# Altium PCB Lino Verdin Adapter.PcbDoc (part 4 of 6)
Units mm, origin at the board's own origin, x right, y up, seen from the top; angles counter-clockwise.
Board outline 69.6 x 35 mm, 8 copper layers (Top Layer, Mid 1, GND 1, Mid 2, Mid 3, GND 2, Mid 4, Bottom Layer), stack 1.198 mm thick; 208 components, 258 nets, 1063 pads, 1090 vias.
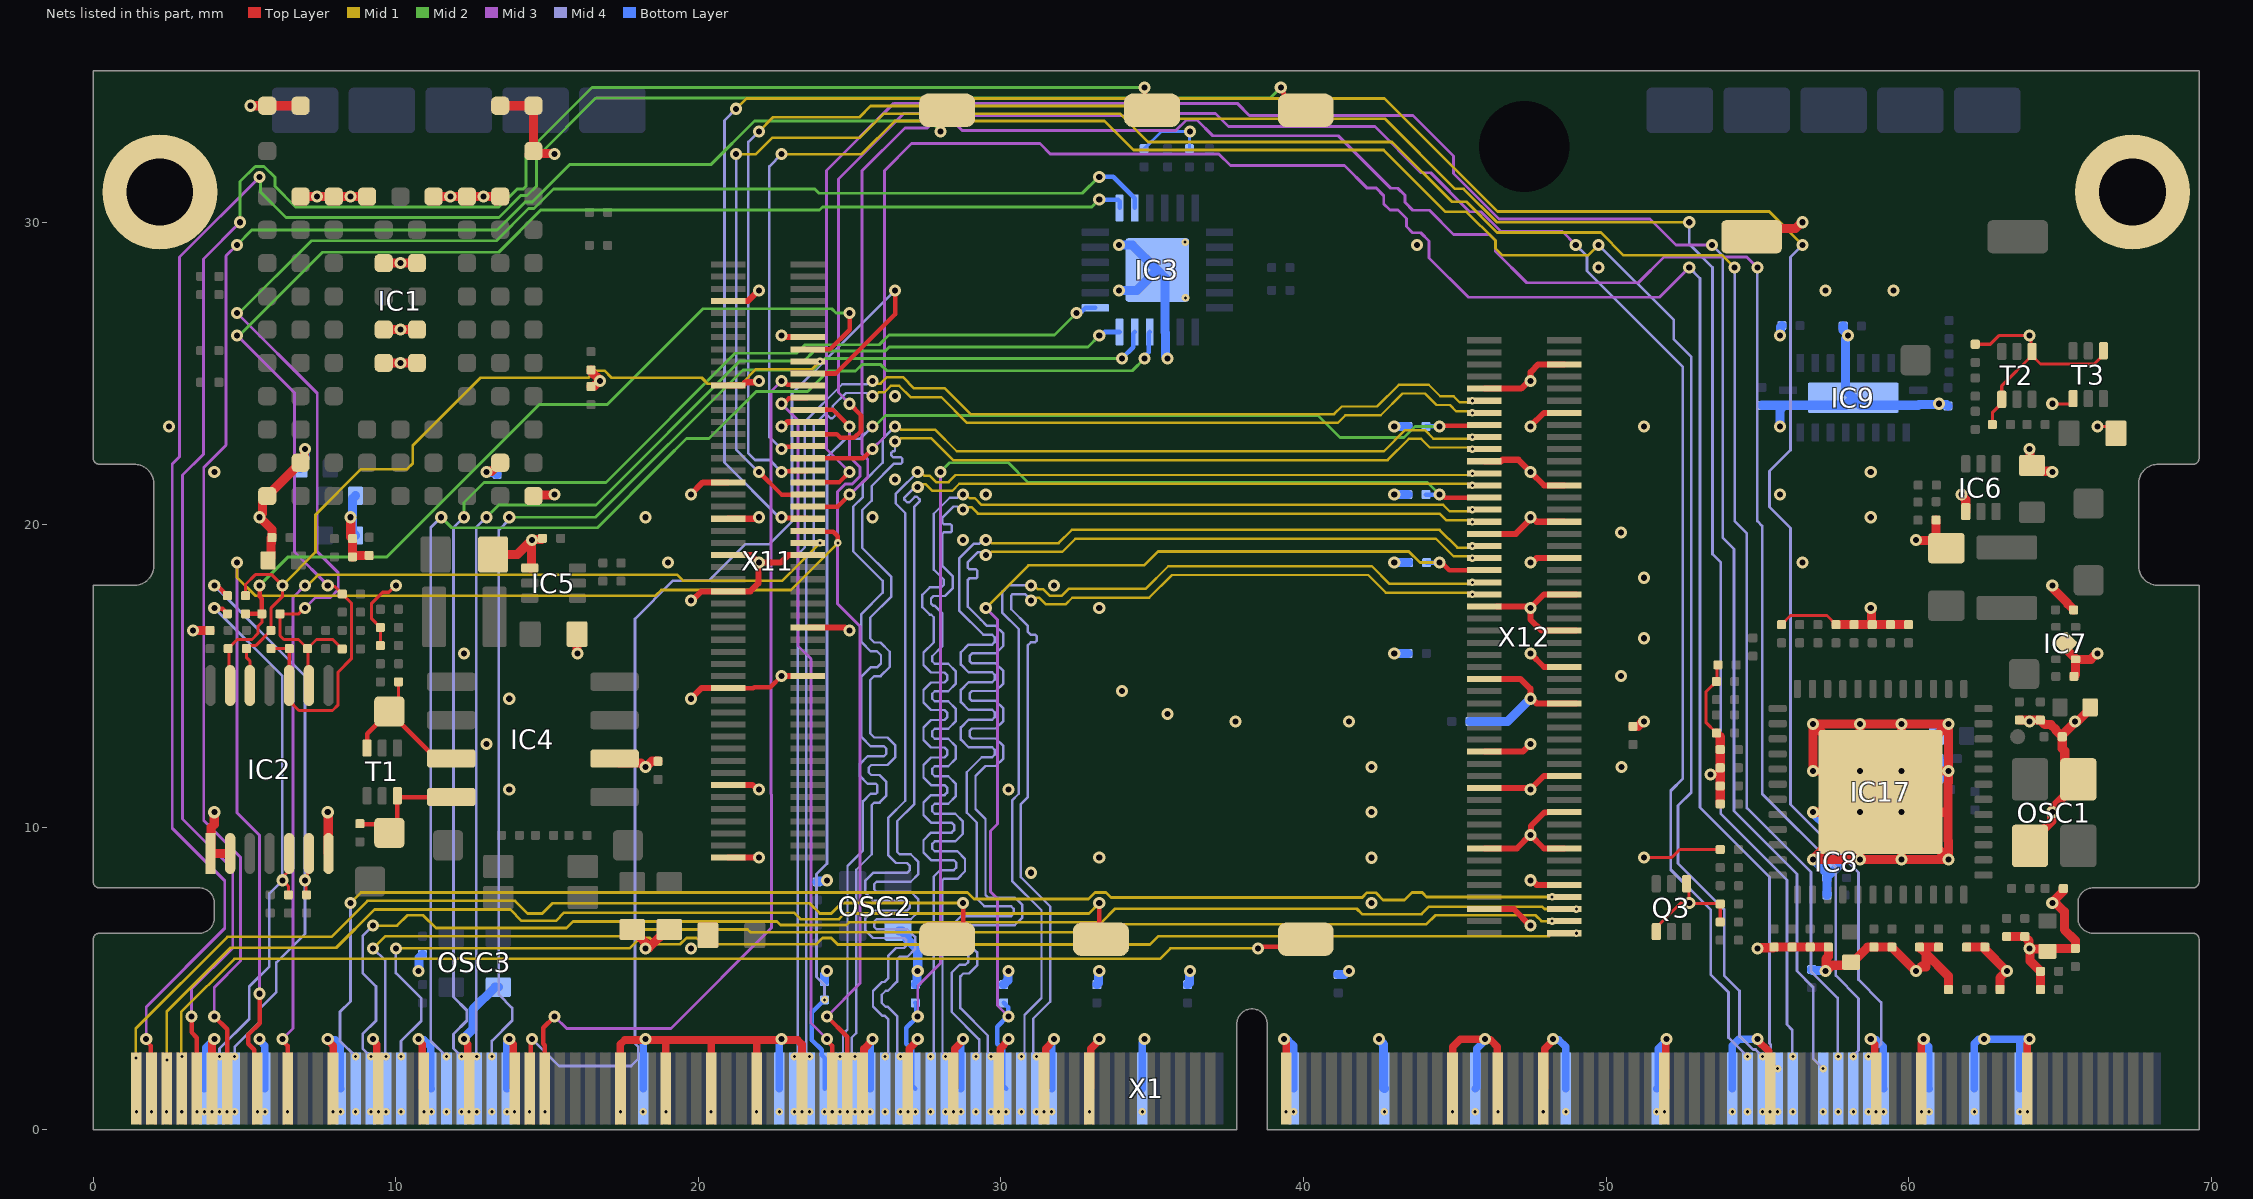
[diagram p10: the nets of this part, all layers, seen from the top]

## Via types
v1: diameter 0.4, hole 0.2, Top Layer to Bottom Layer, tented both sides, 600 vias
v2: diameter 0.25, hole 0.1, Mid 4 to Bottom Layer, tented both sides, 229 vias
v3: diameter 0.25, hole 0.1, Top Layer to Mid 1, tented both sides, 216 vias
v4: diameter 0.25, hole 0.1, Top Layer to Mid 1, tented top, 41 vias
v5: diameter 0.4, hole 0.2, Top Layer to Bottom Layer, 4 vias

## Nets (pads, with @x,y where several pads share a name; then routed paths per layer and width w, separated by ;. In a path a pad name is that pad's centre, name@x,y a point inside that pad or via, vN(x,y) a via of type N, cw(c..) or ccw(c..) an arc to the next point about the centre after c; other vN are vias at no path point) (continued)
GND: C1.1 C2.1 C3.1 C4.1 C5.1 C6.1 C7.1 C8.1 C9.1 C10.1 C11.1 C12.1 C13.1 C14.1 C16.1 C17.1 C18.1 C20.1 C21.1 C22.1 C23.1 C24.1 C25.1 C27.1 C28.1 C29.1 C30.1 C31.1 C32.1 C33.2 C34.1 C35.1 C36.1 C37.1 C38.1 C39.1 C40.1 C41.1 C42.1 C43.1 C44.1 C45.1 C46.1 C47.1 C48.1 C49.1 C50.1 C51.1 C124.1 C125.2 C126.2 C127.1 C128.1 C129.1 C130.1 C131.1 C132.1 C133.1 C134.1 C135.1 C136.1 C137.1 C138.1 C139.1 C140.1 C141.1 C142.1 C143.1 C144.1 C145.1 C146.1 C147.1 C148.1 C173.1 C174.1 C175.1 C176.1 IC1.A1 IC1.A9 IC1.B2 IC1.B8 IC1.E4 IC1.E5 IC1.F4 IC1.F5 IC1.H4 IC1.H5 IC1.K2 IC1.K3 IC1.K4 IC1.K6 IC1.K7 IC1.K8 IC1.L1 IC1.M1 IC1.M2 IC1.M8 IC1.M9 IC2.1 IC2.2 IC2.7 IC3.9 IC3.25 IC4.6 IC5.1 IC6.1 IC7.2 IC7.5 IC8.2 IC8.5 IC9.5 IC9.11 IC9.20 IC9.21 IC17.49 OSC1.2 OSC1.4 OSC2.2 OSC3.2 pad.2 Q3.1 Q3.4 R7.1 R8.1 R33.2 R35.2 R39.1 R42.1 R44.1 R47.1 R49.1 R86.1 R87.1 R88.1 R95.1 R96.1 R97.1 R98.1 R123.1 R124.1 SW1.2 T2.1 T2.4 T3.1 T3.4 X1.10 X1.11 X1.18 X1.27 X1.28 X1.33 X1.39 X1.40 X1.45 X1.50 X1.51 X1.65 X1.68 X1.71 X1.77 X1.83 X1.86 X1.89 X1.97 X1.98 X1.103 X1.109 X1.110 X1.115 X1.121 X1.122 X1.127 X1.134 X1.145 X1.146 X1.158 X1.167 X1.170 X1.173 X1.179 X1.182 X1.194 X1.195 X1.204 X1.209 X1.223 X1.224 X1.229 X1.230 X1.236 X1.242 X1.243 X11.P7 X11.P14 X11.P21 X11.P28 X11.P37 X11.P43 X11.P49 X11.P50 X11.P55 X11.P62 X11.P70 X11.P71 X11.P87 X11.P99 X12.S6 X12.S9 X12.S14 X12.S21 X12.S26 X12.S32 X12.S33 X12.S38 X12.S44 X12.S45 X12.S50 X12.S56 X12.S57 X12.S62 X12.S69 X12.S74 X12.S75 X12.S80 X12.S85 X12.S86 X12.S92 X12.S95 | length 324.5
  Top Layer w0.1: R33.2@9.489,16.008 R35.2@9.489,16.608 9.189,16.908 9.189,17.391 9.568,17.77 9.77,17.77 v1(10,18) ; v1(51.25,9) 52.17,9 52.44,9.27 R97.1@53.775,9.27 ; Q3.1@51.66,6.555 51.66,6.69 52.463,7.492 52.742,7.492 v1(52.75,7.5) ; Q3.4@52.66,8.135 52.75,8.045 v1(52.75,7.5) ; R123.1@53.65,13.12 53.3,13.47 53.3,14.47 53.675,14.845 53.675,15.345 R88.1@53.718,15.388 ; R95.1@53.775,6.87 R96.1@53.775,7.47 53.76,7.485 52.765,7.485 v1(52.75,7.5) ; R87.1@55.8,16.7 56.1,17 57.3,17 R86.1@57.6,16.7 ; 59.21,16.74 59.36,16.74 C141.1@59.4,16.7 ; R44.1@62.204,25.967 62.702,25.967 62.984,26.25 v1(64,26.25) 64.04,26.21 64.04,25.768 T2.1@64.079,25.728 64.079,25.592 64.09,25.581 64.092,25.581 64.357,25.316 66.139,25.316 66.439,25.616 T3.4@66.439,25.751 ; R47.1@62.77,23.313 62.77,23.704 63.079,24.013 63.079,24.593 T2.1@64.079,25.593 ; v1(64.75,24) 65.339,24 65.439,24.1 T3.1@65.439,24.171 ; v1(66.25,23.25) 66.625,23.25 C34.1@66.852,23.023
  Top Layer w0.15: X11.P71@20.98,14.6 21.82,14.6 21.845,14.625 22.375,14.625 v1(22.75,15)
  Top Layer w0.2: v1(19.75,14.25) 20.1,14.6 X11.P71@20.98,14.6 ; v1(19.75,17.5) 19.804,17.5 20.104,17.8 21.72,17.8 21.983,18.063 21.983,18.733 v1(22,18.75) ; v1(19.75,21) 20.15,21.4 X11.P37@20.98,21.4 ; X11.P99@20.98,9 v1(22,9) ; X11.P87@20.98,11.4 21.796,11.4 21.946,11.25 v1(22,11.25) ; X11.P49@20.98,19 21.75,19 v1(22,18.75) ; X11.P43@20.98,20.2 21.896,20.2 21.946,20.25 v1(22,20.25) ; X11.P21@20.98,24.6 21.45,24.6 21.55,24.7 21.633,24.7 21.645,24.712 21.962,24.712 v1(22,24.75) ; X11.P7@20.98,27.4 21.643,27.4 21.993,27.75 v1(22,27.75) ; v1(22.75,15) X11.P70@23.62,15 ; v1(22.75,23.25) 22.804,23.25 22.954,23.4 X11.P28@23.62,23.4 ; v1(22.75,26.25) 22.804,26.25 22.854,26.2 X11.P14@23.62,26.2 ; X11.P62@23.62,16.6 24.846,16.6 24.946,16.5 v1(25,16.5) ; X11.P50@23.62,19 22.97,19 22.72,18.75 v1(22,18.75) ; X12.S95@45.98,7.3 46.95,7.3 v1(47.5,6.75) ; X12.S85@45.98,9.3 47.05,9.3 v1(47.5,9.75) ; X12.S75@45.98,11.3 47.396,11.3 47.446,11.25 v1(47.5,11.25) 47.95,11.7 X12.S74@48.62,11.7 ; X12.S69@45.98,12.5 47.25,12.5 v1(47.5,12.75) ; X12.S33@45.98,19.7 47.016,19.7 47.462,20.146 47.462,20.212 v1(47.5,20.25) 47.554,20.25 47.704,20.1 X12.S32@48.62,20.1 ; X12.S21@45.98,22.1 46.534,22.1 46.584,22.15 47.1,22.15 v1(47.5,21.75) 47.95,21.3 X12.S26@48.62,21.3 ; X12.S9@45.98,24.5 47.196,24.5 47.446,24.75 v1(47.5,24.75) 47.509,24.759 47.509,25.049 47.76,25.3 X12.S6@48.62,25.3 ; X12.S57@46.38,14.9 47.18,14.9 47.5,14.58 v1@47.5,14.257 ; X12.S45@46.38,17.3 47.396,17.3 47.446,17.25 v1(47.5,17.25) ; v1(47.5,8.25) 47.554,8.25 47.704,8.1 X12.S92@48.62,8.1 ; v1(47.5,14.25) 47.554,14.25 47.704,14.1 X12.S62@48.62,14.1 X12.S62@49.02,14.1 ; v1(47.5,15.75) 47.95,15.3 X12.S56@49.02,15.3 ; v1(47.5,18.75) 47.554,18.75 47.704,18.9 X12.S38@48.62,18.9 ; v1(47.5,23.25) 47.95,23.7 X12.S14@48.62,23.7 ; 48.03,10.49 47.96,10.49 47.514,10.044 47.514,9.764 v1(47.5,9.75) ; X12.S86@48.62,9.3 47.95,9.3 v1(47.5,9.75) ; X12.S50@49.02,16.5 47.87,16.5 47.5,16.87 v1(47.5,17.25) ; X12.S44@49.02,17.7 47.95,17.7 v1(47.5,17.25)
  Top Layer w0.25: X1.11@3.925,1.362 3.925,2.884 4,2.959 v1(4,3) ; v1(7.75,3) 7.75,2.959 7.925,2.784 X1.27@7.925,1.362 ; v1(9.25,3) 9.25,2.959 9.375,2.834 9.375,1.412 X1.33@9.425,1.362 ; v1(10.75,3) 10.75,2.959 10.875,2.834 10.875,1.412 X1.39@10.925,1.362 ; v1(12.25,3) 12.25,2.959 12.375,2.834 12.375,1.412 X1.45@12.425,1.362 ; v1(13.75,3) 13.75,2.959 13.875,2.834 13.875,1.412 X1.51@13.925,1.362 ; X1.65@17.425,1.362 17.425,2.825 17.571,2.971 18.221,2.971 v1(18.25,3) 18.279,2.971 18.925,2.971 ; X1.71@18.925,1.362 18.925,2.971 ; X1.77@20.425,1.362 20.425,2.971 ; X1.83@21.925,1.362 21.925,2.971 ; X1.89@23.425,1.362 23.425,2.825 23.279,2.971 22.779,2.971 v1(22.75,3) 22.721,2.971 21.925,2.971 ; X1.97@25.425,1.362 25.475,1.412 25.475,2.684 25.75,2.959 v1(25.75,3) ; X1.103@26.925,1.362 26.975,1.412 26.975,2.684 27.25,2.959 v1(27.25,3) ; X1.109@28.425,1.362 28.475,1.412 28.475,2.684 28.75,2.959 v1(28.75,3) ; X1.115@29.925,1.362 29.975,1.412 29.975,2.684 30.25,2.959 v1(30.25,3) ; X1.121@31.425,1.362 31.475,1.412 31.475,2.684 31.75,2.959 v1(31.75,3) ; X1.127@32.925,1.362 32.975,1.412 32.975,2.684 33.25,2.959 v1(33.25,3) ; v1(39.35,3) 39.35,2.959 39.425,2.884 X1.145@39.425,1.362 ; X1.167@44.925,1.362 44.93,1.368 44.93,2.75 45.18,3 v1(46,3) 46.029,2.971 46.182,2.971 46.412,2.742 46.412,1.376 X1.173@46.425,1.362 ; X1.179@47.925,1.362 47.975,1.412 47.975,2.684 48.25,2.959 v1(48.25,3) ; X1.195@51.925,1.362 51.975,1.412 51.975,2.975 v1(52,3) ; v1@53.42,11.77 53.775,11.77 ; v1(55,3) 55,2.968 55.375,2.593 55.375,1.412 X1.209@55.425,1.362 ; v1(58.75,3) 58.75,2.959 58.875,2.834 58.875,1.412 X1.223@58.925,1.362 ; X1.229@60.425,1.362 60.425,2.884 60.5,2.959 v1(60.5,3) ; X1.243@63.925,1.362 63.925,2.884 64,2.959 v1(64,3) ; 18.925,2.971 20.425,2.971 ; 20.425,2.971 21.925,2.971
  Top Layer w0.3: v1(3.3,16.5) 3.308,16.508 C10.1@3.86,16.508 ; v1(4,10.5) 4,10.1 3.895,9.995 3.895,9.157 IC2.1@3.875,9.137 IC2.2@4.525,9.137 ; v1(5.2,33.85) IC1.M9@5.75,33.85 IC1.M8@6.85,33.85 ; C6.1@5.781,18.825 5.881,18.925 5.881,19.399 5.884,19.402 C7.1@5.884,19.556 ; C7.1@5.902,19.575 5.902,19.848 v1(5.5,20.25) 5.5,20.277 5.6,20.377 5.6,20.8 IC1.A9@5.75,20.95 5.9,21.1 IC1.B8@6.85,22.05 6.981,22.181 6.981,22.481 v1(7,22.5) ; IC1.K8@6.85,30.85 v1(7.4,30.85) IC1.K7@7.95,30.85 v1(8.5,30.85) IC1.K6@9.05,30.85 ; v1(7.75,10.5) 7.767,10.483 7.767,9.145 IC2.7@7.775,9.137 ; v1(8.5,20.25) 8.51,20.24 8.51,19.6 C5.1@8.57,19.54 C4.1@8.57,18.94 8.617,18.987 C8.1@9.12,18.987 ; IC1.E5@9.6,25.35 v1(10.15,25.35) IC1.E4@10.7,25.35 ; IC1.F5@9.6,26.45 v1(10.15,26.45) IC1.F4@10.7,26.45 ; IC1.H5@9.6,28.65 v1(10.15,28.65) IC1.H4@10.7,28.65 ; IC1.K4@11.25,30.85 v1(11.8,30.85) IC1.K3@12.35,30.85 v1(12.9,30.85) IC1.K2@13.45,30.85 ; v1(13,21.75) 13.019,21.769 13.169,21.769 IC1.B2@13.45,22.05 ; C20.1@13.216,19.018 14.018,19.018 v1@14.481,19.481 ; IC1.M2@13.45,33.85 IC1.M1@14.55,33.85 IC1.L1@14.55,32.35 14.631,32.269 15.231,32.269 v1(15.25,32.25) ; IC5.1@14.426,18.573 14.481,18.573 v1@14.481,19.481 ; IC1.A1@14.55,20.95 14.581,20.981 15.231,20.981 v1(15.25,21) ; R39.1@14.847,19.553 14.814,19.519 14.519,19.519 v1(14.5,19.5) v1@14.481,19.481 ; C22.1@15.991,16.385 15.995,16.381 15.995,15.755 v1(16,15.75) ; R7.1@16.45,24.57 16.543,24.57 16.723,24.75 v1(16.75,24.75) 16.75,24.777 16.45,25.077 R8.1@16.45,25.121 ; IC4.6@17.23,12.272 17.38,12.122 18.101,12.122 18.223,12 v1(18.25,12) 18.277,12 18.46,12.183 C21.1@18.666,12.183 ; C23.1@17.816,6.623 17.891,6.623 18.091,6.423 18.091,6.348 18.231,6.208 18.231,6.019 v1(18.25,6) 18.269,6.019 18.362,6.019 18.966,6.623 C24.1@19.041,6.623 ; C45.1@50.89,13.34 51.063,13.34 51.223,13.5 v1(51.25,13.5) ; R123.1@53.65,13.12 53.775,12.995 53.775,11.77 C175.1@53.775,10.77 ; SW1.2@54.81,29.52 55.077,29.787 56.26,29.787 56.473,30 v1(56.5,30) ; v1(55,6) 55.019,6.019 55.527,6.019 C133.1@55.55,6.042 C143.1@56.15,6.042 C128.1@56.75,6.042 C130.1@57.35,6.042 57.35,5.734 57.269,5.654 57.269,5.269 v1(57.25,5.25) 57.277,5.25 57.469,5.442 58,5.442 C129.1@58.1,5.542 58.15,5.542 58.65,6.042 C138.1@58.85,6.042 C174.1@59.45,6.042 60.242,5.25 60.277,5.25 60.437,5.41 60.552,5.41 ; v1(56.84,10.5) v5(58.4,10.5) ; R86.1@57.6,16.7 C173.1@58.2,16.7 C139.1@58.8,16.7 ; v1(58.75,17.25) 58.769,17.231 58.769,16.731 C139.1@58.8,16.7 ; C146.1@60,16.7 C141.1@59.4,16.7 C139.1@58.8,16.7 ; v1(60.25,19.5) 60.269,19.481 C27.1@60.996,19.481 ; 60.419,5.392 60.57,5.392 ; 60.57,5.422 60.57,5.832 ; R42.1@60.91,20.163 60.91,19.566 C27.1@60.996,19.481 ; C127.1@60.99,6.042 C131.1@60.36,6.042 60.57,5.832 ; C27.1@61.25,19.227 C27.1@60.996,19.481 ; C126.2@61.32,4.642 61.32,5.082 60.57,5.832 ; v1(61.75,21) 61.75,20.973 61.89,20.833 IC6.1@61.89,20.437 ; C124.1@61.92,6.042 R124.1@62.52,6.042 62.52,5.98 v1(63.25,5.25) 63.246,5.25 63.02,5.024 C125.2@63.02,4.642 ; C132.1@63.24,6.39 C134.1@63.84,6.39 63.981,6.249 63.981,6.019 v1@64.019,5.981 ; C148.1@63.663,13.545 C176.1@64.353,13.545 64.503,13.395 64.704,13.395 64.879,13.219 64.879,13.195 C14.1@65.079,12.995 ; v1(64,22.5) 64.019,22.481 64.019,22.023 C29.1@64.078,21.964 64.273,21.769 64.731,21.769 v1(64.75,21.75) ; OSC1.4@64.011,9.387 64.011,9.487 64.731,10.207 64.731,10.481 v1(64.75,10.5) 64.769,10.519 64.769,10.645 65.611,11.487 OSC1.2@65.611,11.587 65.161,12.037 65.161,12.519 65.079,12.601 C14.1@65.079,12.995 ; C18.1@64.36,4.642 C17.1@64.36,5.242 64.019,5.582 v1@64.019,5.981 ; v1(64.75,18) 64.769,17.981 64.769,17.898 65.254,17.414 65.254,17.389 C31.1@65.454,17.189 ; C13.1@65.113,7.98 65.113,7.89 64.75,7.527 v1(64.75,7.5) 64.769,7.481 64.885,7.481 65.15,7.216 65.15,6.62 65.51,6.26 C16.1@65.51,5.997 64.685,5.997 C135.1@64.59,5.902 64.511,5.981 v1@64.019,5.981 ; IC7.5@65.195,16.089 65.195,15.899 65.52,15.574 IC7.2@65.52,15.554 ; C30.1@65.465,14.989 65.52,15.044 IC7.2@65.52,15.554 ; C147.1@66.003,13.967 66.003,13.917 65.605,13.519 65.519,13.519 v1(65.5,13.5) 65.5,13.473 65.079,13.052 C14.1@65.079,12.995 ; v1(66.25,15.75) 66.224,15.75 66.028,15.554 IC7.2@65.52,15.554 ; v1(56.84,13.42) v1(58.4,13.42) ; v1(56.84,13.42) v5(58.4,11.86) ; v1(56.84,13.42) v1(56.84,11.86) v5(58.4,11.86) ; v1(58.4,8.94) v1(59.76,8.94) ; v1(58.4,8.94) v5(58.4,10.5) ; v1(58.4,8.94) v1(56.84,8.94) v5(58.4,10.5) ; v5(58.4,10.5) IC17.49@59.08,11.18 ; v5(58.4,10.5) v5(59.76,10.5) ; v5(58.4,10.5) v5(58.4,11.86) ; v5(58.4,11.86) v1(58.4,13.42) ; v5(58.4,11.86) v5(59.76,11.86) ; v5(58.4,11.86) IC17.49@59.08,11.18 ; v1(58.4,13.42) v1(59.76,13.42) ; IC17.49@59.08,11.18 v5(59.76,11.86) ; IC17.49@59.08,11.18 v5(59.76,10.5) ; v1(59.76,8.94) v1(61.32,8.94) ; v1(59.76,8.94) v5(59.76,10.5) ; v5(59.76,10.5) 61.3,10.5 ; v5(59.76,10.5) v5(59.76,11.86) ; v5(59.76,10.5) v1(61.32,8.94) ; v5(59.76,11.86) v1(61.32,13.42) ; v5(59.76,11.86) v1(61.32,11.86) ; v5(59.76,11.86) v1(59.76,13.42) ; v1(59.76,13.42) v1(61.32,13.42) ; 61.3,10.5 61.3,11.459 61.32,11.479 v1(61.32,11.86) ; 61.3,10.5 61.3,9.564 61.32,9.544 v1(61.32,8.94) ; v1(61.32,11.86) v1(61.32,13.42)
  Bottom Layer w0.1: v1(13.75,3) v1@13.75,3.081 ; C11.1@34.735,32.43 35.305,33 v1(36.25,33) 36.24,32.99 36.24,32.44 C12.1@36.23,32.43
  Bottom Layer w0.25: X1.10@3.675,1.362 3.715,1.403 3.715,2.715 v1(4,3) ; v1(5.5,3) 5.5,2.959 5.675,2.784 X1.18@5.675,1.362 ; v1(7.75,3) 7.779,2.971 7.996,2.971 8.162,2.806 8.162,1.376 X1.28@8.175,1.362 ; v1(10.75,3) 10.779,2.971 10.932,2.971 11.162,2.742 11.162,1.376 X1.40@11.175,1.362 ; v1(12.25,3) v1@12.258,3.007 ; X1.50@13.675,1.362 13.675,2.884 13.75,2.959 v1(13.75,3) ; X1.68@18.175,1.362 18.175,2.884 18.25,2.959 v1(18.25,3) ; X1.86@22.675,1.362 22.675,2.884 22.75,2.959 v1(22.75,3) ; X1.98@25.675,1.362 25.675,2.884 25.75,2.959 v1(25.75,3) ; X1.110@28.675,1.362 28.675,2.884 28.75,2.959 v1(28.75,3) ; X1.122@31.675,1.362 31.675,2.884 31.75,2.959 v1(31.75,3) ; X1.134@34.675,1.362 34.675,2.884 34.75,2.959 v1(34.75,3) ; v1(39.35,3) 39.379,2.971 39.488,2.971 39.675,2.784 X1.146@39.675,1.362 ; X1.170@45.675,1.362 45.725,1.412 45.725,2.684 46,2.959 v1(46,3) ; v1(48.25,3) 48.279,2.971 48.432,2.971 48.662,2.742 48.662,1.376 X1.182@48.675,1.362 ; X1.194@51.675,1.362 51.725,1.412 51.725,2.684 52,2.959 v1(52,3) ; X1.204@54.175,1.362 54.175,2.785 54.39,3 v1(55,3) ; v1(58.75,3) 58.779,2.971 58.932,2.971 59.162,2.742 59.162,1.376 X1.224@59.175,1.362 ; v1@60.432,2.971 60.662,2.742 60.662,1.376 X1.230@60.675,1.362 ; X1.236@62.175,1.362 62.175,2.854 62.321,3 63.675,3 ; X1.242@63.675,1.362 63.675,3 ; v1(64,3) 63.675,3
  Bottom Layer w0.3: C1.1@6.832,21.86 6.932,21.96 6.932,22.122 6.995,22.186 6.995,22.495 v1(7,22.5) ; C2.1@8.67,19.65 8.57,19.75 8.57,20.153 8.5,20.223 v1(8.5,20.25) 8.5,20.277 8.57,20.347 8.57,20.86 C3.1@8.67,20.96 ; v1(10.75,5.25) 10.769,5.269 10.769,5.684 C51.1@10.885,5.8 ; v1(12.25,3) 12.25,3.027 12.55,3.327 12.55,3.983 13.285,4.718 OSC3.2@13.385,4.718 ; v1(13,21.75) 13.019,21.731 13.289,21.731 C9.1@13.35,21.67 ; C50.1@23.93,8.2 23.961,8.231 24.231,8.231 v1(24.25,8.25) ; C36.1@24.17,4.9 24.17,5.143 24.25,5.223 v1(24.25,5.25) ; v1@25.736,3.014 v1(25.75,3) v1@25.769,3.019 ; OSC2.2@26.625,6.575 26.725,6.575 26.9,6.4 26.9,6.3 27.25,5.95 v1(27.25,5.25) 27.231,5.231 27.231,4.861 C38.1@27.17,4.8 ; C40.1@30.09,4.8 30.231,4.941 30.231,5.231 v1(30.25,5.25) ; C42.1@33.17,4.8 33.231,4.861 33.231,5.231 v1(33.25,5.25) ; v1(33.9,27.75) 34.498,27.75 IC3.25@35.17,28.422 ; v1(33.9,29.25) 33.906,29.244 34.348,29.244 IC3.25@35.17,28.422 ; v1(35.5,25.5) 35.5,25.527 35.445,25.582 35.445,26.347 IC3.9@35.42,26.372 35.42,28.172 IC3.25@35.17,28.422 ; C44.1@36.17,4.8 36.231,4.861 36.231,5.231 v1(36.25,5.25) ; C46.1@41.15,5.13 41.353,5.13 41.473,5.25 v1(41.5,5.25) ; v1(42.5,3) 42.5,2.973 42.65,2.823 42.65,1.387 X1.158@42.675,1.362 ; v1(43,15.75) C41.1@43.46,15.75 ; v1(43,18.75) C39.1@43.47,18.75 ; v1(43,21) C37.1@43.45,21 ; v1(43,23.25) C35.1@43.45,23.25 ; C43.1@45.5,13.5 46.75,13.5 v1(47.5,14.25) ; C47.1@55.15,23.94 55.16,23.95 IC9.20@56.02,23.95 ; v1(55.75,23.25) 55.75,23.805 55.895,23.95 IC9.20@56.02,23.95 ; v1(55.75,26.25) 55.769,26.269 55.769,26.539 R49.1@55.81,26.58 ; C28.1@56.8,5.3 56.831,5.269 57.231,5.269 v1(57.25,5.25) ; v1(56.84,8.94) 56.85,8.94 57.25,8.54 ; v1(56.84,10.5) 56.84,10.484 57.292,10.033 C33.2@57.292,9.961 ; C32.1@57.297,7.761 57.297,8.323 IC8.2@57.3,8.326 57.3,8.346 57.625,8.671 IC8.5@57.625,8.861 ; C49.1@57.84,26.57 57.84,26.437 58,26.277 v1(58,26.25) 58,26.223 57.92,26.143 IC9.5@57.92,25.35 57.92,24.45 IC9.21@58.17,24.2 ; C142.1@60.79,11.25 60.79,11.33 v1(61.32,11.86) 61.32,11.887 61.01,12.197 C145.1@61.01,12.27 ; C136.1@60.92,13.02 60.92,13.07 61.251,13.401 61.301,13.401 v1(61.32,13.42) ; C48.1@61.3,23.93 61.249,23.981 61.019,23.981 v1(61,24) 60.973,24 60.948,23.975 60.345,23.975 IC9.11@60.32,23.95 58.42,23.95 IC9.21@58.17,24.2 ; IC9.20@56.02,23.95 57.92,23.95 IC9.21@58.17,24.2
  other v1: 62.5,3 60.25,5.25 19.75,6 64,6 42.245,7.495 31,8.5 33.25,9 42.245,8.995 42.245,10.505 13.75,11.25 30.25,11.25 53.45,11.75 42.25,12 50.505,11.995 13,12.75 37.75,13.5 41.5,13.5 64,13.5 35.5,13.75 13.75,14.25 34,14.5 50.5,15 12.25,15.75 51.25,16.25 33.25,17.25 31.75,18 51.25,18.25 19,18.75 56.5,18.75 28.75,19.5 50.5,19.75 18.25,20.25 25.75,20.25 58.75,20.25 29.5,21 55.75,21 26.5,21.5 4,21.75 58.75,21.75 2.5,23.25 51.25,23.25 26.5,24.25 57.25,27.75 59.5,27.75 49.75,28.5 43.75,29.25
  other v2: 3.675,0.6 5.675,0.6 8.175,0.6 11.175,0.6 13.675,0.6 18.175,0.6 22.675,0.6 25.675,0.6 28.675,0.6 31.675,0.6 34.675,0.6 39.675,0.6 42.675,0.6 45.675,0.6 48.675,0.6 51.675,0.6 54.175,0.6 59.175,0.6 60.675,0.6 62.175,0.6 63.675,0.6 36.1,27.5 36.09,29.34
  other v3: 3.925,0.6 7.925,0.6 9.425,0.6 10.925,0.6 12.425,0.6 13.925,0.6 17.425,0.6 18.925,0.6 20.425,0.6 21.925,0.6 23.425,0.6 25.425,0.6 26.925,0.6 28.425,0.6 29.925,0.6 31.425,0.6 32.925,0.6 39.425,0.6 44.925,0.6 46.425,0.6 47.925,0.6 51.925,0.6 55.425,0.6 58.925,0.6 60.425,0.6 63.925,0.6
GPIO_1: X1.206 X11.P30 | length 67.2
  Top Layer w0.15: X11.P30@23.62,23 24.573,23 24.698,22.875 25.155,22.875 25.375,23.095 25.375,23.625 v1(25,24)
  Mid 3 w0.095: v1(25,24) 24.63,24.37 24.63,31.43 26.79,33.59 28.7,33.59 28.77,33.52 35.8,33.52 35.87,33.59 37.09,33.59 37.52,33.16 42.36,33.16 43.885,31.635 44.205,31.635 45.493,30.348 45.873,30.348 46.531,29.689 48.561,29.689 v1(49,29.25)
  Mid 4 w0.09: v1(49,29.25) 49.37,28.88 49.37,28.392 52.54,25.222 52.54,11.61 52.14,11.21 52.14,8.598 53.46,7.278 53.46,5.14 54.05,4.55 54.05,3.05 v2(54.675,2.425)
  other v2: 54.675,0.6
GPIO_2: X1.208 X11.P32 | length 70.1
  Top Layer w0.15: v1(22.75,22.5) 22.818,22.5 22.893,22.575 23.595,22.575 X11.P32@23.62,22.6
  Mid 4 w0.09: v1(22.75,22.5) 22.345,22.905 22.345,31.845 v1(22.75,32.25) ; v1(49.75,29.25) 49.757,29.25 52.24,26.767 52.24,26.13 52.82,25.55 52.82,11.16 52.38,10.72 52.38,8.81 53.905,7.285 53.905,5.107 54.415,4.597 54.415,3.097 54.857,2.655 54.945,2.655 v2(55.175,2.425)
  Mid 1 w0.09: v1(22.75,32.25) 25.4,32.25 26.495,33.345 33.425,33.345 34.38,32.39 42.65,32.39 44.695,30.345 45.393,30.345 46.345,29.393 46.345,29.135 46.575,28.905 46.833,28.905 49.405,28.905 v1(49.75,29.25)
  other v2: 55.175,0.6
GPIO_3: X1.210 X11.P34 | length 69.4
  Top Layer w0.15: X11.P34@23.62,22.2 25.449,22.2 v1(25.75,22.5)
  Mid 3 w0.095: v1(25.75,22.5) 26.15,22.9 26.15,31.7 27.048,32.598 31.292,32.598 31.64,32.25 37.21,32.25 37.59,31.87 41.36,31.87 42.092,31.138 42.392,31.138 42.653,30.878 42.653,30.606 42.856,30.403 43.128,30.403 43.402,30.128 43.402,29.856 43.606,29.653 43.877,29.653 44.152,29.378 44.152,28.818 45.45,27.52 51.77,27.52 v1(52.75,28.5)
  Mid 4 w0.09: v1(52.75,28.5) 53.105,28.145 53.105,10.655 55.405,8.355 55.405,2.857 55.445,2.817 55.445,2.255 v2(55.675,2.025)
  other v2: 55.675,0.6
GPIO_4: X1.212 X11.P36 | length 74.7
  Top Layer w0.15: v1(22.75,21.75) 22.775,21.775 23.595,21.775 X11.P36@23.62,21.8
  Mid 4 w0.09: v1(22,33) 21.65,32.65 21.65,22.362 21.872,22.14 22.36,22.14 v1(22.75,21.75) ; v1(52.75,30) 52.75,29.28 53.52,28.51 53.52,19.03 53.795,18.755 53.795,10.445 55.98,8.26 55.98,3.48 56.155,3.305 56.155,2.445 v2(56.175,2.425)
  Mid 1 w0.09: v1(22,33) 22.47,33.47 25.32,33.47 25.69,33.84 34.76,33.84 35.18,33.42 42.7,33.42 45.015,31.105 45.295,31.105 46.4,30 v1(52.75,30)
  other v2: 56.175,0.6
GPIO_5: X1.216 X11.P38 | length 73
  Top Layer w0.15: X11.P38@23.62,21.4 24.65,21.4 v1(25,21.75)
  Mid 3 w0.095: v1(25,21.75) 24.24,22.51 24.24,31.71 26.46,33.93 37.81,33.93 38.21,33.53 43.62,33.53 44.957,32.193 44.957,31.613 46.46,30.11 51.45,30.11 52.31,29.25 v1(53.5,29.25)
  Mid 4 w0.09: v1(53.5,29.25) 53.86,28.89 53.86,19.57 54.23,19.2 54.23,10.54 56.31,8.46 56.31,5.25 56.845,4.715 56.845,2.355 v2(57.175,2.025)
  other v2: 57.175,0.6
GPIO_6: X1.218 X11.P40 | length 75.9
  Top Layer w0.15: v1(22,21.75) 22.75,21 X11.P40@23.62,21
  Mid 4 w0.09: v1@21.23,32.25 21.25,32.23 21.25,22.493 21.993,21.75 v1(22,21.75) ; v1(54.25,28.5) 54.25,20.12 54.655,19.715 54.655,10.635 56.772,8.518 56.772,5.24 57.655,4.357 57.655,2.445 v2(57.675,2.425)
  Mid 1 w0.09: v1(21.25,32.25) 21.9,32.25 22.44,32.79 25.33,32.79 26.13,33.59 33.93,33.59 34.865,32.655 42.925,32.655 44.9,30.68 45.38,30.68 46.4,29.66 49.828,29.66 50.583,28.905 53.845,28.905 v1(54.25,28.5)
  other v2: 57.675,0.6
GPIO_7: X1.220 X11.P42 | length 73.8
  Top Layer w0.15: X11.P42@23.62,20.6 24.6,20.6 v1(25,21)
  Mid 3 w0.095: v1(25,21) 25.017,21 25.6,21.583 25.6,22.159 25.403,22.356 25.403,31.688 26.834,33.12 27.57,33.12 27.83,33.38 28.37,33.38 28.72,33.03 35.78,33.03 36.13,33.38 36.48,33.38 37,32.86 41.149,32.86 42.884,31.125 43.116,31.125 43.361,30.88 43.361,30.647 43.613,30.396 44.164,30.396 44.963,29.598 46.144,29.598 46.347,29.394 46.347,29.033 47.38,28 51.066,28 51.913,28.847 54.652,28.847 v1(55,28.5)
  Mid 4 w0.09: v1(55,28.5) 55,20.12 55.16,19.96 55.16,11.11 57.595,8.675 57.595,5.096 58.345,4.346 58.345,2.623 58.175,2.453 v2(58.175,2.425)
  other v2: 58.175,0.6
GPIO_8: X1.222 X11.P44 | length 81.8
  Top Layer w0.15: v1(22.75,20.25) 22.775,20.225 23.595,20.225 X11.P44@23.62,20.2
  Mid 4 w0.09: v1(21.25,33.75) 20.86,33.36 20.86,22.06 22.67,20.25 v1(22.75,20.25) ; v1(56.5,29.25) 56.095,28.845 56.095,22.465 55.405,21.775 55.405,20.585 56.095,19.895 56.095,10.757 58.345,8.507 58.345,4.965 59.095,4.215 59.095,2.845 v2(58.675,2.425)
  Mid 1 w0.09: v1(21.25,33.75) 21.59,34.09 42.677,34.09 46.412,30.355 55.395,30.355 v1(56.5,29.25)
  other v2: 58.675,0.6
GPIO_9: X1.17 X11.P46 | length 40.6
  Top Layer w0.15: X1.17@5.425,1.362 5.325,1.462 5.325,2.645 5.125,2.845 5.125,3.155 5.5,3.53 v1(5.5,4.5) ; X11.P46@23.62,19.8 23.645,19.775 24.455,19.775 24.61,19.62 v4(24.61,19.4)
  Mid 3 w0.095: v1(4.75,18.75) 4.75,10.48 5.5,9.73 v1(5.5,4.5)
  Mid 1 w0.09: v1(4.75,18.75) 4.75,18.262 5.357,17.655 18.585,17.655 18.775,17.845 23.055,17.845 v4(24.61,19.4)
  other v3: 5.425,0.6
GPIO_10: X1.21 X11.P48 | length 34.8
  Top Layer w0.15: v1(6.25,3) 6.25,2.95 6.425,2.775 X1.21@6.425,1.362
  Mid 3 w0.095: v1(6.25,3) 6.598,3.348 6.598,17.597 v1(7,18)
  Mid 1 w0.09: v1(7,18) 7.079,18 7.424,18.345 19.305,18.345 19.495,18.155 22.775,18.155 v3(24.02,19.4)
  other v3: 6.425,0.6
I2C_1_ADAPTER_SCL: IC2.10 IC3.19 R17.1 R20.2 R28.1 | length 49.5
  Top Layer w0.1: R20.2@5.871,15.908 R17.1@6.48,15.908 6.478,15.905 6.478,14.69 IC2.10@6.475,14.687 6.475,14.18 6.795,13.86 7.908,13.86 8.095,14.047 8.095,15.135 8.53,15.57 8.53,16.079 8.53,17.412 R28.1@8.23,17.712 7.989,17.953 7.797,17.953 v1(7.75,18)
  Mid 3 w0.095: v1(4.75,26.25) 4.767,26.25 6.653,24.365 6.653,19.097 v1(7.75,18)
  Mid 2 w0.095: v1(4.75,26.25) 4.82,26.25 7.58,29.01 13.4,29.01 14.79,30.4 24,30.4 24.1,30.5 33,30.5 v1(33.25,30.75)
  Bottom Layer w0.15: v1(33.25,30.75) 33.87,30.75 33.92,30.7 IC3.19@33.92,30.472
I2C_1_ADAPTER_SCL_3V3: IC4.4 R27.1 T1.6 TP12.1 | length 4.2
  Top Layer w0.15: R27.1@8.812,10.121 8.827,10.106 9.497,10.106 TP12.1@9.787,9.816 10.05,10.079 T1.6@10.05,11.043 10.091,11.002 IC4.4@11.83,11.002
I2C_1_ADAPTER_SDA: IC2.9 IC3.20 R16.1 R19.2 R31.1 | length 49.5
  Top Layer w0.1: R19.2@6.139,17.058 6.791,17.058 6.984,17.25 v1(7,17.25) ; R19.2@6.171,17.058 6.171,16.334 6.297,16.208 6.78,16.208 R16.1@7.08,15.908 ; IC2.9@7.125,14.687 7.103,14.71 7.103,15.885 R16.1@7.08,15.908 ; R31.1@8.23,15.896 7.919,16.208 7.38,16.208 R16.1@7.08,15.908
  Mid 3 w0.095: v1(4.75,27) 7.402,24.348 7.402,19.108 8.098,18.412 8.098,17.856 7.839,17.598 7.348,17.598 v1(7,17.25)
  Mid 2 w0.095: v1(4.75,27) 4.82,27 7.21,29.39 13.33,29.39 14.39,30.45 14.564,30.45 15.212,31.097 23.848,31.097 23.988,30.958 32.69,30.958 33.233,31.5 v1(33.25,31.5)
  Bottom Layer w0.15: v1(33.25,31.5) 33.717,31.5 34.42,30.797 IC3.20@34.42,30.472
I2C_1_ADAPTER_SDA_3V3: IC4.3 R30.1 T1.3 TP13.1 | length 5.3
  Top Layer w0.1: TP13.1@9.787,13.833 10.088,14.134 R30.1@10.089,14.808 R30.1@10.089,14.808
  Top Layer w0.15: T1.3@9.05,12.623 9.05,13.096 TP13.1@9.787,13.833 9.787,13.823 11.338,12.272 IC4.3@11.83,12.272
I2C_1_SCL: IC2.12 R9.1 R12.1 R20.1 X11.P18 | length 28.1
  Top Layer w0.1: R9.1@5.033,17.658 5.033,18.028 5.355,18.35 5.9,18.35 v1(6.25,18) 6.25,17.62 5.871,17.241 5.871,16.875 R20.1@5.871,16.508 5.366,16.003 5.156,16.003 R12.1@5.06,15.908 5.06,15.62 5.175,15.505 IC2.12@5.175,14.687
  Mid 1 w0.09: v1(6.25,18) 7.345,19.095 7.345,20.333 8.852,21.84 10.372,21.84 10.56,22.028 10.56,22.62 12.8,24.86 16.372,24.86 16.607,25.095 16.893,25.095 17.129,24.859 20.111,24.859 20.31,24.66 21.422,24.66 21.907,25.145 23.765,25.145 v4(24.02,25.4)
I2C_1_SDA: IC2.13 R10.1 R11.1 R19.1 X11.P16 | length 30.2
  Top Layer w0.1: IC2.13@4.525,14.687 4.493,14.72 4.493,15.875 R11.1@4.46,15.908 4.76,16.208 5.243,16.208 5.44,16.405 5.44,16.64 5.571,16.771 R19.1@5.571,17.058
  Top Layer w0.15: R10.1@5.033,17.058 R19.1@5.539,17.058 ; v1(5.5,18) 5.5,17.63 5.571,17.559 R19.1@5.571,17.058 ; X11.P16@23.62,25.8 24.35,25.8 25,26.45 v1(25,27)
  Mid 2 w0.095: v1(5.5,18) 6.43,18.93 9.689,18.93 14.729,23.97 16.98,23.97 20.15,27.14 24.41,27.14 24.55,27 v1(25,27)
I2C_1_VERDIN_SCL: IC2.6 R9.2 R14.2 X1.14 | length 19.8
  Top Layer w0.1: R14.2@7.05,7.77 7.025,7.795 7.025,8.225 v1(7,8.25) 7,8.331 7.079,8.41 7.079,9.091 IC2.6@7.125,9.137
  Top Layer w0.15: v1(4,18) 4.048,17.952 4.139,17.952 R9.2@4.433,17.658
  Mid 4 w0.09: v1(4,18) 7,15 v1(7,8.25) 7,6.48 6.05,5.53 6.05,4.562 5.54,4.052 5.54,3.61 4.675,2.745 v2(4.675,2.425)
  other v2: 4.675,0.6
I2C_1_VERDIN_SDA: IC2.5 R10.2 R13.2 X1.12 | length 18.7
  Top Layer w0.1: R13.2@6.45,7.77 6.45,8.05 v1(6.25,8.25) 6.307,8.307 6.307,8.397 6.475,8.564 IC2.5@6.475,9.137
  Top Layer w0.15: v1(4,17.25) 4.03,17.22 4.272,17.22 R10.2@4.433,17.058
  Mid 4 w0.09: v1(4,17.25) 6.25,15 v1(6.25,8.25) 5.82,7.82 5.82,5.4 5.155,4.735 5.155,3.667 4.175,2.687 v2(4.175,2.425)
  other v2: 4.175,0.6
I2C_2_SCL: X1.55 X11.P22 | length 30.4
  Top Layer w0.15: X1.55@14.925,1.362 14.925,2.795 14.875,2.845 14.875,3.375 v1(15.25,3.75) ; v1(22.75,24.75) 22.818,24.75 22.943,24.625 23.595,24.625 X11.P22@23.62,24.6
  Mid 3 w0.095: v1(15.25,3.75) 15.65,3.35 19.091,3.35 22.42,6.679 22.42,11.089 22.402,11.106 22.402,24.402 v1(22.75,24.75)
  other v3: 14.925,0.6
I2C_2_SDA: X1.53 X11.P20 | length 40.3
  Top Layer w0.15: X1.53@14.425,1.362 14.463,1.4 14.463,2.962 v1(14.5,3) ; X11.P20@23.62,25 24.54,25 26.5,26.96 v1(26.5,27.75)
  Mid 4 w0.09: v1(14.5,3) 15.39,2.11 17.78,2.11 18.01,2.34 18.01,2.752 17.905,2.857 17.905,14.708 17.905,16.893 19.167,18.155 20.355,18.155 21.56,19.36 22.348,19.36 23.095,20.107 23.095,21.214 23.095,21.982 23.095,22.357 23.095,22.802 23.095,24.345 v1(26.5,27.75)
  other v3: 14.425,0.6
I2C_3_SCL: X1.95 X11.P26 | length 25.1
  Top Layer w0.15: X11.P26@23.62,23.8 24.45,23.8 v1(25,23.25) ; v1(24.25,3.75) 24.925,3.075 X1.95@24.925,1.362
  Mid 3 w0.095: v1(24.25,3.75) 25.348,4.848 25.348,16.644 24.6,17.391 24.6,21.091 24.856,21.348 25.089,21.348 25.348,21.606 25.348,21.902 25,22.25 v1(25,23.25)
  other v3: 24.925,0.6
I2C_3_SDA: X1.93 X11.P24 | length 24.3
  Top Layer w0.15: v1(22.75,24) 22.818,24 22.993,24.175 23.595,24.175 X11.P24@23.62,24.2 ; v1(24.25,3) 24.25,2.95 24.425,2.775 X1.93@24.425,1.362
  Mid 3 w0.095: v1(22.75,24) 23.293,23.457 23.293,16.275 23.293,15.997 23.72,15.57 23.72,3.53 v1(24.25,3)
  other v3: 24.425,0.6
I2S_1_BCLK: X1.30 X12.S94 | length 45.9
  Mid 4 w0.09: v1(8.5,7.5) 8.5,4.25 8.155,3.905 8.155,2.945 v2(8.675,2.425)
  Mid 1 w0.09: v1(8.5,7.5) 8.845,7.845 28.893,7.845 29.108,7.63 32.892,7.63 33.107,7.845 33.475,7.845 33.64,7.68 41.942,7.68 42.102,7.84 42.388,7.84 42.628,7.6 43.34,7.6 43.585,7.845 43.925,7.845 44.07,7.7 v3(48.22,7.7)
  other v2: 8.675,0.6
I2S_1_D_IN: X1.36 X12.S100 | length 43.9
  Mid 4 w0.09: v1(10,6) 10,5.184 10.845,4.339 10.845,3.607 10.175,2.937 v2(10.175,2.425)
  Mid 1 w0.09: v1(10,6) 17.72,6 18.065,6.345 18.393,6.345 18.598,6.14 19.402,6.14 19.607,6.345 19.935,6.345 20.14,6.14 23.902,6.14 24.107,6.345 24.393,6.345 24.608,6.13 34.93,6.13 35.205,6.405 48.119,6.405 48.214,6.5 v3(49.02,6.5)
  other v2: 10.175,0.6
I2S_1_D_OUT: X1.34 X12.S98 | length 43.3
  Mid 4 w0.09: v1(9.25,6) 9.655,5.595 9.655,2.445 v2(9.675,2.425)
  Mid 1 w0.09: v1(9.25,6) 9.655,6.405 17.675,6.405 17.89,6.62 21.63,6.62 21.715,6.535 33.755,6.535 34.02,6.8 44.062,6.8 44.357,7.095 47.669,7.095 47.864,6.9 v3(48.22,6.9)
  other v2: 9.675,0.6
I2S_1_SYNC: X1.32 X12.S96 | length 45.6
  Mid 4 w0.09: v2(9.175,2.425) 8.905,2.695 8.905,3.167 9.345,3.607 9.345,4.744 8.905,5.184 8.905,6.405 v1(9.25,6.75)
  Mid 1 w0.09: v1(9.25,6.75) 10.04,6.75 10.385,7.095 10.905,7.095 11.33,6.67 15.635,6.67 15.855,6.89 22.6,6.89 22.715,6.775 24.895,6.775 24.98,6.86 33.32,6.86 33.77,7.31 41.76,7.31 41.94,7.13 43.9,7.13 44.15,7.38 47.89,7.38 47.97,7.3 v3(49.02,7.3)
  other v2: 9.175,0.6
I2S_2_BCLK: IC3.10 X1.42 | length 45
  Mid 2 w0.095: v1(11.5,20.25) 11.848,19.903 16.661,19.903 18.856,22.098 19.606,22.848 20.356,22.848 21.911,24.403 23.613,24.403 24.29,25.08 25.192,25.08 25.404,25.293 26.028,25.293 26.23,25.09 34.34,25.09 v1(34.75,25.5)
  Mid 4 w0.09: v1(11.5,20.25) 11.155,19.905 11.155,2.945 v2(11.675,2.425)
  Bottom Layer w0.15: v1(34.75,25.5) 34.75,25.568 34.879,25.697 34.879,26.33 IC3.10@34.92,26.372
  other v2: 11.675,0.6
I2S_2_D_IN: IC3.11 X1.48 | length 41.9
  Mid 2 w0.095: v1(13.75,20.25) 16.6,20.25 21.47,25.12 23.807,25.12 24.187,25.5 v1(34,25.5)
  Mid 4 w0.09: v2(13.175,2.425) 13.175,2.937 13.845,3.607 13.845,4.035 13.405,4.475 13.405,19.826 13.75,20.171 v1(13.75,20.25)
  Bottom Layer w0.15: v1(34,25.5) 34.37,25.87 34.37,26.322 IC3.11@34.42,26.372
  other v2: 13.175,0.6
I2S_2_D_OUT: IC3.12 X1.46 | length 41.4
  Mid 2 w0.095: v1(13,20.25) 13.402,20.653 16.613,20.653 21.37,25.41 23.49,25.41 23.83,25.75 26.18,25.75 26.31,25.88 32.88,25.88 v1(33.25,26.25)
  Mid 4 w0.09: v2(12.675,2.425) 12.655,2.445 12.655,19.905 v1(13,20.25)
  Bottom Layer w0.15: v1(33.25,26.25) 33.318,26.25 33.439,26.372 IC3.12@33.92,26.372
  other v2: 12.675,0.6
I2S_2_SYNC: IC3.13 X1.44 | length 42.5
  Mid 2 w0.095: v1(12.25,20.25) 12.25,20.741 12.911,21.402 16.943,21.402 21.21,25.67 23.24,25.67 23.52,25.95 25.98,25.95 26.3,26.27 31.77,26.27 v1(32.5,27)
  Mid 4 w0.09: v2(12.175,2.425) 11.905,2.695 11.905,3.167 12.345,3.607 12.345,3.955 11.905,4.395 11.905,19.905 v1(12.25,20.25)
  Bottom Layer w0.15: v1(32.5,27) 32.548,27.048 32.671,27.048 32.795,27.172 IC3.13@33.12,27.172
  other v2: 12.175,0.6
JTAG_1_TCK: X1.9 X29.1 | length 66
  Top Layer w0.15: v1(3.25,3.75) 3.25,3.22 3.425,3.045 X1.9@3.425,1.362 ; v1(34.75,34.45) 34.75,33.945 X29.1@34.995,33.7
  Mid 3 w0.095: v1(3.25,3.75) 3.25,4.66 4.61,6.02 4.61,8.62 2.953,10.278 2.953,21.643 3.64,22.33 3.64,28.79 v1(4.85,30)
  Mid 2 w0.095: v1(4.85,30) 4.85,31.341 5.356,31.848 5.644,31.848 6.003,31.489 6.003,31.189 6.689,30.503 13.413,30.503 14.013,31.103 14.211,31.103 14.3,31.191 14.3,32.27 16.48,34.45 v1(34.75,34.45)
  other v3: 3.425,0.6
JTAG_1_TDI: X1.1 X21.1 | length 32.1
  Top Layer w0.15: X21.1@28.225,6.3 28.29,6.3 28.75,6.76 v1(28.75,7.5)
  Mid 1 w0.09: v4(1.41,2.37) 1.405,2.375 1.405,3.345 4.44,6.38 7.87,6.38 9.06,7.57 13.942,7.57 14.357,7.155 14.84,7.155 15.175,7.49 23.68,7.49 24.015,7.155 24.393,7.155 24.738,7.5 v1(28.75,7.5)
  other v3: 1.425,0.6
JTAG_1_TDO: X1.5 X23.1 | length 35.6
  Top Layer w0.15: v1(33.25,7.5) 33.25,6.355 X23.1@33.305,6.3
  Mid 1 w0.09: v4(2.43,2.31) 2.43,3.92 4.53,6.02 8.032,6.02 9.297,7.285 13.785,7.285 14.16,6.91 15.29,6.91 15.56,7.18 23.16,7.18 23.375,6.965 24.655,6.965 24.845,7.155 32.905,7.155 v1(33.25,7.5)
  other v3: 2.425,0.6
JTAG_1_TMS: X1.13 X32.1 | length 55.3
  Top Layer w0.15: v1(4,3.75) 4.425,3.325 X1.13@4.425,1.362 ; v1(28,33) 28,33.475 X32.1@28.225,33.7
  Mid 3 w0.095: v1(4,3.75) 4,4.71 4.87,5.58 4.87,9.01 3.65,10.23 3.65,21.891 4.39,22.631 4.39,28.89 v1(4.75,29.25)
  Mid 2 w0.095: v1(4.75,29.25) 5.24,29.74 13.35,29.74 14.28,30.67 14.508,30.67 15.741,31.902 20.411,31.902 21.856,33.347 27.653,33.347 v1(28,33)
  other v3: 4.425,0.6
JTAG_1_TRST#: X1.3 X27.1 | length 71.4
  Top Layer w0.15: v1(1.75,3) 1.75,2.932 1.907,2.775 1.907,1.38 X1.3@1.925,1.362 ; v1(39.25,34.45) 39.25,34.382 39.348,34.284 39.348,34.16 39.808,33.7 X27.1@40.075,33.7
  Mid 3 w0.095: v1(1.75,3) 1.75,4.065 4.347,6.663 4.347,8.233 2.61,9.97 2.61,22.01 2.848,22.248 2.848,28.848 v1(5.5,31.5)
  Mid 2 w0.095: v1(5.5,31.5) 5.522,31.478 5.522,31.008 6.37,30.16 13.41,30.16 14.13,30.88 14.34,30.88 14.65,31.19 14.65,32.141 16.611,34.102 38.903,34.102 v1(39.25,34.45)
  other v3: 1.925,0.6
JTAG_1_VREF: X1.7 X26.1 | length 39.7
  Top Layer w0.15: v1(38.5,6) 38.548,6.048 39.823,6.048 X26.1@40.075,6.3
  Mid 1 w0.09: v4(2.93,2.42) 2.905,2.445 2.905,3.893 4.667,5.655 35.255,5.655 35.6,6 v1(38.5,6)
  other v3: 2.925,0.6
MSP_1/2_N: X1.88 X12.S11 | length 45
  Mid 4 w0.08: v2(23.175,2.425) 23.175,2.452 23.28,2.557 23.28,19.02 23.52,19.26 23.52,23.411 24.754,24.645 25.558,24.645 25.663,24.75 v1(25.75,24.75)
  Mid 1 w0.08: v1(25.75,24.75) 25.837,24.75 25.923,24.664 26.023,24.664 26.239,24.88 26.761,24.88 27.131,24.51 28.148,24.51 28.998,23.66 41.014,23.66 41.264,23.91 42.433,23.91 43.153,24.63 44.139,24.63 44.519,24.25 44.96,24.25 45.165,24.045 45.479,24.045 45.534,24.1 v3(45.58,24.1)
  other v2: 23.175,0.6
MSP_1/2_P: X1.90 X12.S13 | length 45
  Mid 4 w0.08: v2(23.675,2.425) 23.675,2.452 23.57,2.557 23.57,18.9 23.81,19.139 23.81,23.29 24.169,23.65 24.24,23.65 24.367,23.523 24.433,23.523 24.572,23.662 24.572,23.728 24.443,23.857 24.443,23.924 24.874,24.355 25.558,24.355 25.663,24.25 v1(25.75,24.25)
  Mid 1 w0.08: v1(25.75,24.25) 25.837,24.25 25.961,24.374 26.143,24.374 26.359,24.59 26.641,24.59 27.011,24.22 28.028,24.22 28.878,23.37 41.134,23.37 41.384,23.62 42.553,23.62 43.273,24.34 44.019,24.34 44.399,23.96 44.84,23.96 45.045,23.755 45.479,23.755 45.534,23.7 v3(45.58,23.7)
  other v2: 23.675,0.6
MSP_3: C35.2 C36.2 X1.92 X12.S15 | length 44.7
  Top Layer w0.15: v1(44.5,23.25) 44.525,23.275 45.955,23.275 X12.S15@45.98,23.3
  Mid 2 w0.095: v1(25.75,23.25) 25.82,23.25 26.18,23.61 40.48,23.61 41.21,22.88 43.32,22.88 43.69,23.25 v1(44.5,23.25)
  Mid 4 w0.09: v2(24.17,4.3) 24.17,4.79 23.905,5.055 23.905,8.455 24.25,8.8 24.25,22.238 24.857,22.845 25.345,22.845 v1(25.75,23.25)
  Bottom Layer w0.15: v2(24.17,4.3) 23.75,3.88 23.75,2.97 24.075,2.645 24.075,2.475 24.175,2.375 X1.92@24.175,1.362 ; C35.2@44.05,23.25 v1(44.5,23.25)
  other v2: 24.175,0.6
MSP_4/5_N: X1.94 X12.S17 | length 45
  Mid 4 w0.08: v2(24.675,2.425) 24.675,2.452 24.78,2.557 24.78,3.17 24.93,3.32 24.93,8.72 25.44,9.23 25.44,10.857 25.692,11.109 25.87,11.109 25.917,11.156 25.917,11.392 25.87,11.439 25.592,11.439 25.34,11.692 25.34,12.097 25.592,12.349 26.131,12.349 26.213,12.432 26.213,12.597 26.131,12.679 25.692,12.679 25.39,12.982 25.39,13.46 25.39,14.986 25.692,15.288 25.905,15.288 26.037,15.421 26.037,15.686 25.905,15.818 25.692,15.818 25.39,16.121 25.39,16.366 25.39,17.053 26.09,17.753 26.09,18.15 25.12,19.12 25.12,20.6 25.44,20.92 25.44,21.4 26.09,22.05 26.09,22.84 v1(26.5,23.25)
  Mid 1 w0.08: v1(26.5,23.25) 26.587,23.25 26.692,23.145 27.825,23.145 28.54,22.43 42.661,22.43 43.361,23.13 44.011,23.13 44.296,22.845 45.479,22.845 45.534,22.9 v3(45.58,22.9)
  other v2: 24.675,0.6
MSP_4/5_P: X1.96 X12.S19 | length 45
  Mid 4 w0.08: v2(25.175,2.425) 25.175,2.452 25.07,2.557 25.07,3.05 25.22,3.2 25.22,8.6 25.73,9.11 25.73,10.737 25.812,10.819 25.99,10.819 26.207,11.036 26.207,11.513 25.99,11.729 25.712,11.729 25.63,11.812 25.63,11.977 25.712,12.059 26.251,12.059 26.503,12.312 26.503,12.717 26.251,12.969 25.812,12.969 25.68,13.102 25.68,13.46 25.68,14.866 25.812,14.998 26.025,14.998 26.327,15.301 26.327,15.806 26.025,16.108 25.812,16.108 25.68,16.241 25.68,16.366 25.68,16.933 26.38,17.633 26.38,18.27 25.41,19.24 25.41,20.48 25.73,20.8 25.73,21.28 26.47,22.02 26.693,22.02 26.74,22.067 26.74,22.183 26.693,22.23 26.44,22.23 26.38,22.29 26.38,22.383 26.427,22.43 26.48,22.43 26.5,22.45 v1(26.5,22.75)
  Mid 1 w0.08: v1(26.5,22.75) 26.587,22.75 26.692,22.855 27.705,22.855 28.42,22.14 42.781,22.14 43.481,22.84 43.891,22.84 44.176,22.555 45.479,22.555 45.534,22.5 v3(45.58,22.5)
  other v2: 25.175,0.6
MSP_6/7_N: X1.100 X12.S23 | length 45
  Mid 4 w0.08: v2(26.175,2.425) 26.175,2.452 26.28,2.557 26.28,3.52 26.28,3.645 26.148,3.777 26.074,3.777 25.772,4.08 25.772,4.585 26.074,4.887 26.148,4.887 26.28,5.02 26.28,5.26 26.28,5.5 26.28,5.76 26.532,6.013 26.793,6.013 26.876,6.095 26.876,6.26 26.793,6.343 25.772,6.343 25.52,6.595 25.52,7 25.772,7.253 26.901,7.253 26.983,7.335 26.983,7.5 26.901,7.583 25.772,7.583 25.52,7.835 25.52,8.24 25.772,8.493 26.901,8.493 26.983,8.575 26.983,8.74 26.901,8.823 26.532,8.823 26.28,9.075 26.28,9.32 26.28,10.32 26.84,10.88 26.84,20.391 26.519,20.712 26.519,21.019 26.604,21.104 v1(27.25,21.75)
  Mid 1 w0.08: v1(27.25,21.75) 27.337,21.75 27.461,21.626 27.643,21.626 27.859,21.41 28.269,21.41 28.504,21.645 45.479,21.645 45.534,21.7 v3(45.58,21.7)
  other v2: 26.175,0.6
MSP_6/7_P: X1.102 X12.S25 | length 45
  Mid 4 w0.08: v2(26.675,2.425) 26.675,2.452 26.57,2.557 26.57,3.52 26.57,3.765 26.268,4.067 26.194,4.067 26.062,4.2 26.062,4.465 26.194,4.597 26.268,4.597 26.57,4.9 26.57,5.26 26.57,5.64 26.652,5.723 26.913,5.723 27.166,5.975 27.166,6.38 26.913,6.633 25.892,6.633 25.81,6.715 25.81,6.88 25.892,6.963 27.021,6.963 27.273,7.215 27.273,7.62 27.021,7.873 25.892,7.873 25.81,7.955 25.81,8.12 25.892,8.203 27.021,8.203 27.273,8.455 27.273,8.86 27.021,9.113 26.652,9.113 26.57,9.195 26.57,10.2 27.13,10.76 27.13,20.59 27.312,20.772 27.312,20.838 27.223,20.927 27.157,20.927 26.969,20.739 26.902,20.739 26.809,20.832 26.809,20.899 27.059,21.149 27.062,21.149 27.163,21.25 v1(27.25,21.25)
  Mid 1 w0.08: v1(27.25,21.25) 27.337,21.25 27.423,21.336 27.523,21.336 27.739,21.12 28.389,21.12 28.624,21.355 45.479,21.355 45.534,21.3 v3(45.58,21.3)
  other v2: 26.675,0.6
MSP_8: C37.2 C38.2 X1.104 X12.S27 | length 40.5
  Top Layer w0.15: v1(44.5,21) 44.568,21 44.668,20.9 X12.S27@45.98,20.9
  Mid 3 w0.095: v1(27.25,3.75) 27.25,4.759 28,5.509 v1(28,21.75)
  Mid 2 w0.095: v1(28,21.75) 28.3,22.05 30.25,22.05 30.898,21.403 44.097,21.403 v1(44.5,21)
  Bottom Layer w0.15: C38.2@27.17,4.2 27.21,4.16 27.21,3.79 v1(27.25,3.75) 26.875,3.375 26.875,2.845 27.075,2.645 27.075,1.462 X1.104@27.175,1.362 ; C37.2@44.05,21 v1(44.5,21)
  other v2: 27.175,0.6
MSP_9/10_N: X1.106 X12.S29 | length 45
  Mid 4 w0.08: v2(27.675,2.425) 27.675,2.452 27.78,2.557 27.78,5.443 27.78,8.371 27.997,8.588 28.441,8.588 28.524,8.67 28.524,8.835 28.441,8.918 27.694,8.918 27.442,9.17 27.442,9.575 27.694,9.828 28.369,9.828 28.452,9.91 28.452,10.075 28.369,10.158 27.694,10.158 27.442,10.41 27.442,10.815 27.694,11.068 28.138,11.068 28.22,11.15 28.22,11.315 28.138,11.398 27.694,11.398 27.442,11.65 27.442,12.055 27.694,12.308 28.138,12.308 28.22,12.39 28.22,12.555 28.138,12.638 27.694,12.638 27.442,12.89 27.442,13.295 27.694,13.548 28.138,13.548 28.22,13.63 28.22,13.795 28.138,13.878 27.694,13.878 27.442,14.13 27.442,14.535 27.694,14.788 28.138,14.788 28.22,14.87 28.22,15.035 28.138,15.118 27.694,15.118 27.442,15.37 27.442,15.775 27.78,16.113 27.78,16.82 27.78,16.855 27.78,16.945 27.697,17.027 27.651,17.027 27.399,17.28 27.399,17.685 27.651,17.937 28.032,17.937 28.115,18.02 28.115,18.185 28.032,18.267 27.78,18.52 27.78,19.49 27.78,20.365 28.31,20.895 28.558,20.895 28.663,21 v1(28.75,21)
  Mid 1 w0.08: v1(28.75,21) 28.837,21 28.961,20.876 29.143,20.876 29.359,20.66 44.617,20.66 44.833,20.445 45.479,20.445 45.534,20.5 v3(45.58,20.5)
  other v2: 27.675,0.6
MSP_9/10_P: X1.108 X12.S31 | length 45
  Mid 4 w0.08: v2(28.175,2.425) 28.175,2.452 28.07,2.557 28.07,7.642 28.07,7.763 28.07,8.251 28.117,8.298 28.561,8.298 28.814,8.55 28.814,8.955 28.561,9.208 27.814,9.208 27.732,9.29 27.732,9.455 27.814,9.538 28.489,9.538 28.742,9.79 28.742,10.195 28.489,10.448 27.814,10.448 27.732,10.53 27.732,10.695 27.814,10.778 28.258,10.778 28.51,11.03 28.51,11.435 28.258,11.688 27.814,11.688 27.732,11.77 27.732,11.935 27.814,12.018 28.258,12.018 28.51,12.27 28.51,12.675 28.258,12.928 27.814,12.928 27.732,13.01 27.732,13.175 27.814,13.258 28.258,13.258 28.51,13.51 28.51,13.915 28.258,14.168 27.814,14.168 27.732,14.25 27.732,14.415 27.814,14.498 28.258,14.498 28.51,14.75 28.51,15.155 28.258,15.408 27.814,15.408 27.732,15.49 27.732,15.655 28.07,15.993 28.07,16.82 28.07,17.065 27.818,17.317 27.771,17.317 27.689,17.4 27.689,17.565 27.771,17.647 28.153,17.647 28.405,17.9 28.405,18.305 28.153,18.557 28.07,18.64 28.07,19.49 28.07,19.703 28.117,19.75 28.333,19.75 28.38,19.797 28.38,19.973 28.333,20.02 28.117,20.02 28.07,20.067 28.07,20.245 28.43,20.605 28.558,20.605 28.663,20.5 v1(28.75,20.5)
  Mid 1 w0.08: v1(28.75,20.5) 28.837,20.5 28.923,20.586 29.023,20.586 29.239,20.37 44.497,20.37 44.712,20.155 45.479,20.155 45.534,20.1 v3(45.58,20.1)
  other v2: 28.175,0.6
MSP_11/12_N: X1.112 X12.S35 | length 45
  Mid 4 w0.08: v2(29.175,2.425) 29.175,2.452 29.28,2.557 29.28,2.993 28.37,3.903 28.37,4.92 28.37,5.195 28.635,5.46 28.829,5.46 28.924,5.555 28.924,5.745 28.829,5.84 28.635,5.84 28.37,6.105 28.37,6.35 28.37,6.749 28.682,7.061 30.335,7.061 30.417,7.143 30.417,7.308 30.335,7.391 29.452,7.391 29.2,7.643 29.2,7.888 29.2,10.159 28.87,10.489 28.87,11.49 28.87,11.735 28.87,11.82 29.368,12.318 29.711,12.318 29.794,12.4 29.794,12.565 29.711,12.648 28.927,12.648 28.675,12.9 28.675,13.305 28.927,13.558 29.711,13.558 29.794,13.64 29.794,13.805 29.711,13.888 28.927,13.888 28.675,14.14 28.675,14.545 28.927,14.798 29.711,14.798 29.794,14.88 29.794,15.045 29.711,15.128 28.927,15.128 28.675,15.38 28.675,15.785 28.927,16.038 29.711,16.038 29.794,16.12 29.794,16.285 29.711,16.368 29.422,16.368 28.62,17.17 28.62,18.889 29.107,19.376 29.289,19.376 29.413,19.5 v1(29.5,19.5)
  Mid 1 w0.08: v1(29.5,19.5) 29.587,19.5 29.692,19.395 31.905,19.395 32.34,19.83 44.5,19.83 45.085,19.245 45.479,19.245 45.534,19.3 v3(45.58,19.3)
  other v2: 29.175,0.6
MSP_11/12_P: X1.114 X12.S37 | length 45
  Mid 4 w0.08: v1(29.5,19) 29.413,19 29.327,19.086 29.227,19.086 28.91,18.769 28.91,18.577 28.957,18.53 29.173,18.53 29.22,18.483 29.22,18.277 29.173,18.23 28.96,18.23 28.91,18.18 28.91,17.29 29.335,16.865 29.542,16.658 29.831,16.658 30.084,16.405 30.084,16 29.831,15.748 29.048,15.748 28.965,15.665 28.965,15.5 29.048,15.418 29.831,15.418 30.084,15.165 30.084,14.76 29.831,14.508 29.048,14.508 28.965,14.425 28.965,14.26 29.048,14.178 29.831,14.178 30.084,13.925 30.084,13.52 29.831,13.268 29.048,13.268 28.965,13.185 28.965,13.02 29.048,12.938 29.831,12.938 30.084,12.685 30.084,12.28 29.831,12.028 29.488,12.028 29.16,11.7 29.16,10.609 29.49,10.279 29.49,7.763 29.572,7.681 30.455,7.681 30.707,7.428 30.707,7.023 30.455,6.771 28.802,6.771 28.66,6.628 28.66,6.35 28.66,6.225 28.755,6.13 28.949,6.13 29.214,5.865 29.214,5.435 28.949,5.17 28.755,5.17 28.66,5.075 28.66,4.92 28.66,4.023 29.57,3.113 29.57,2.557 29.675,2.452 v2(29.675,2.425)
  Mid 1 w0.08: v1(29.5,19) 29.587,19 29.692,19.105 32.025,19.105 32.46,19.54 44.38,19.54 44.965,18.955 45.479,18.955 45.534,18.9 v3(45.58,18.9)
  other v2: 29.675,0.6
MSP_13: C39.2 C40.2 X1.116 X12.S39 | length 35.1
  Top Layer w0.15: v1(44.5,18.75) 44.568,18.75 44.818,18.5 X12.S39@45.98,18.5
  Mid 3 w0.095: v1(29.5,17.25) 29.89,16.86 29.89,10.11 29.66,9.88 29.66,7.87 29.89,7.64 29.89,4.11 v1(30.25,3.75)
  Mid 1 w0.09: v1(29.5,17.25) 30.91,18.66 34.73,18.66 35.19,19.12 43.48,19.12 43.85,18.75 v1(44.5,18.75)
  Bottom Layer w0.15: C40.2@30.09,4.2 30.236,4.054 30.236,3.764 v1(30.25,3.75) ; X1.116@30.175,1.362 30.075,1.462 30.075,2.645 29.875,2.845 29.875,3.415 v1@30.21,3.75 ; C39.2@44.07,18.75 v1(44.5,18.75)
  other v2: 30.175,0.6
MSP_14/15_N: X1.118 X12.S41 | length 32.8
  Mid 4 w0.08: v2(30.675,2.425) 30.675,2.452 30.78,2.557 30.78,3.799 31.34,4.359 31.34,7.26 30.37,8.23 30.37,10.889 30.59,11.109 30.59,16.55 30.05,17.09 30.05,17.783 30.267,18 v1(31,18)
  Mid 1 w0.08: v1(31,18) 31.087,18 31.211,17.876 31.393,17.876 31.609,17.66 32.019,17.66 32.239,17.88 34.78,17.88 35.53,18.63 42.26,18.63 42.845,18.045 45.479,18.045 45.534,18.1 v3(45.58,18.1)
  other v2: 30.675,0.6
MSP_14/15_P: X1.120 X12.S43 | length 32.8
  Mid 4 w0.08: v1(31,17.5) 30.79,17.71 30.387,17.71 30.34,17.663 30.34,17.21 30.88,16.67 30.88,16.47 30.98,16.37 31.133,16.37 31.18,16.323 31.18,16.167 31.133,16.12 30.99,16.12 30.88,16.01 30.88,10.989 30.66,10.769 30.66,8.35 31.63,7.38 31.63,4.239 31.07,3.679 31.07,2.557 31.175,2.452 v2(31.175,2.425)
  Mid 1 w0.08: v1(31,17.5) 31.087,17.5 31.173,17.586 31.273,17.586 31.489,17.37 32.139,17.37 32.359,17.59 34.9,17.59 35.65,18.34 42.14,18.34 42.725,17.755 45.479,17.755 45.534,17.7 v3(45.58,17.7)
  other v2: 31.175,0.6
